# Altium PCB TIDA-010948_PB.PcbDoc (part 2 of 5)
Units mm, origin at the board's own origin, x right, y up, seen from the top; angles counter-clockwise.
Board outline 140 x 180 mm, 4 copper layers (Top Layer, Mid-Layer 1, Mid-Layer 2, Bottom Layer), stack 1.554 mm thick; 481 components, 274 nets, 1278 pads, 301 vias.
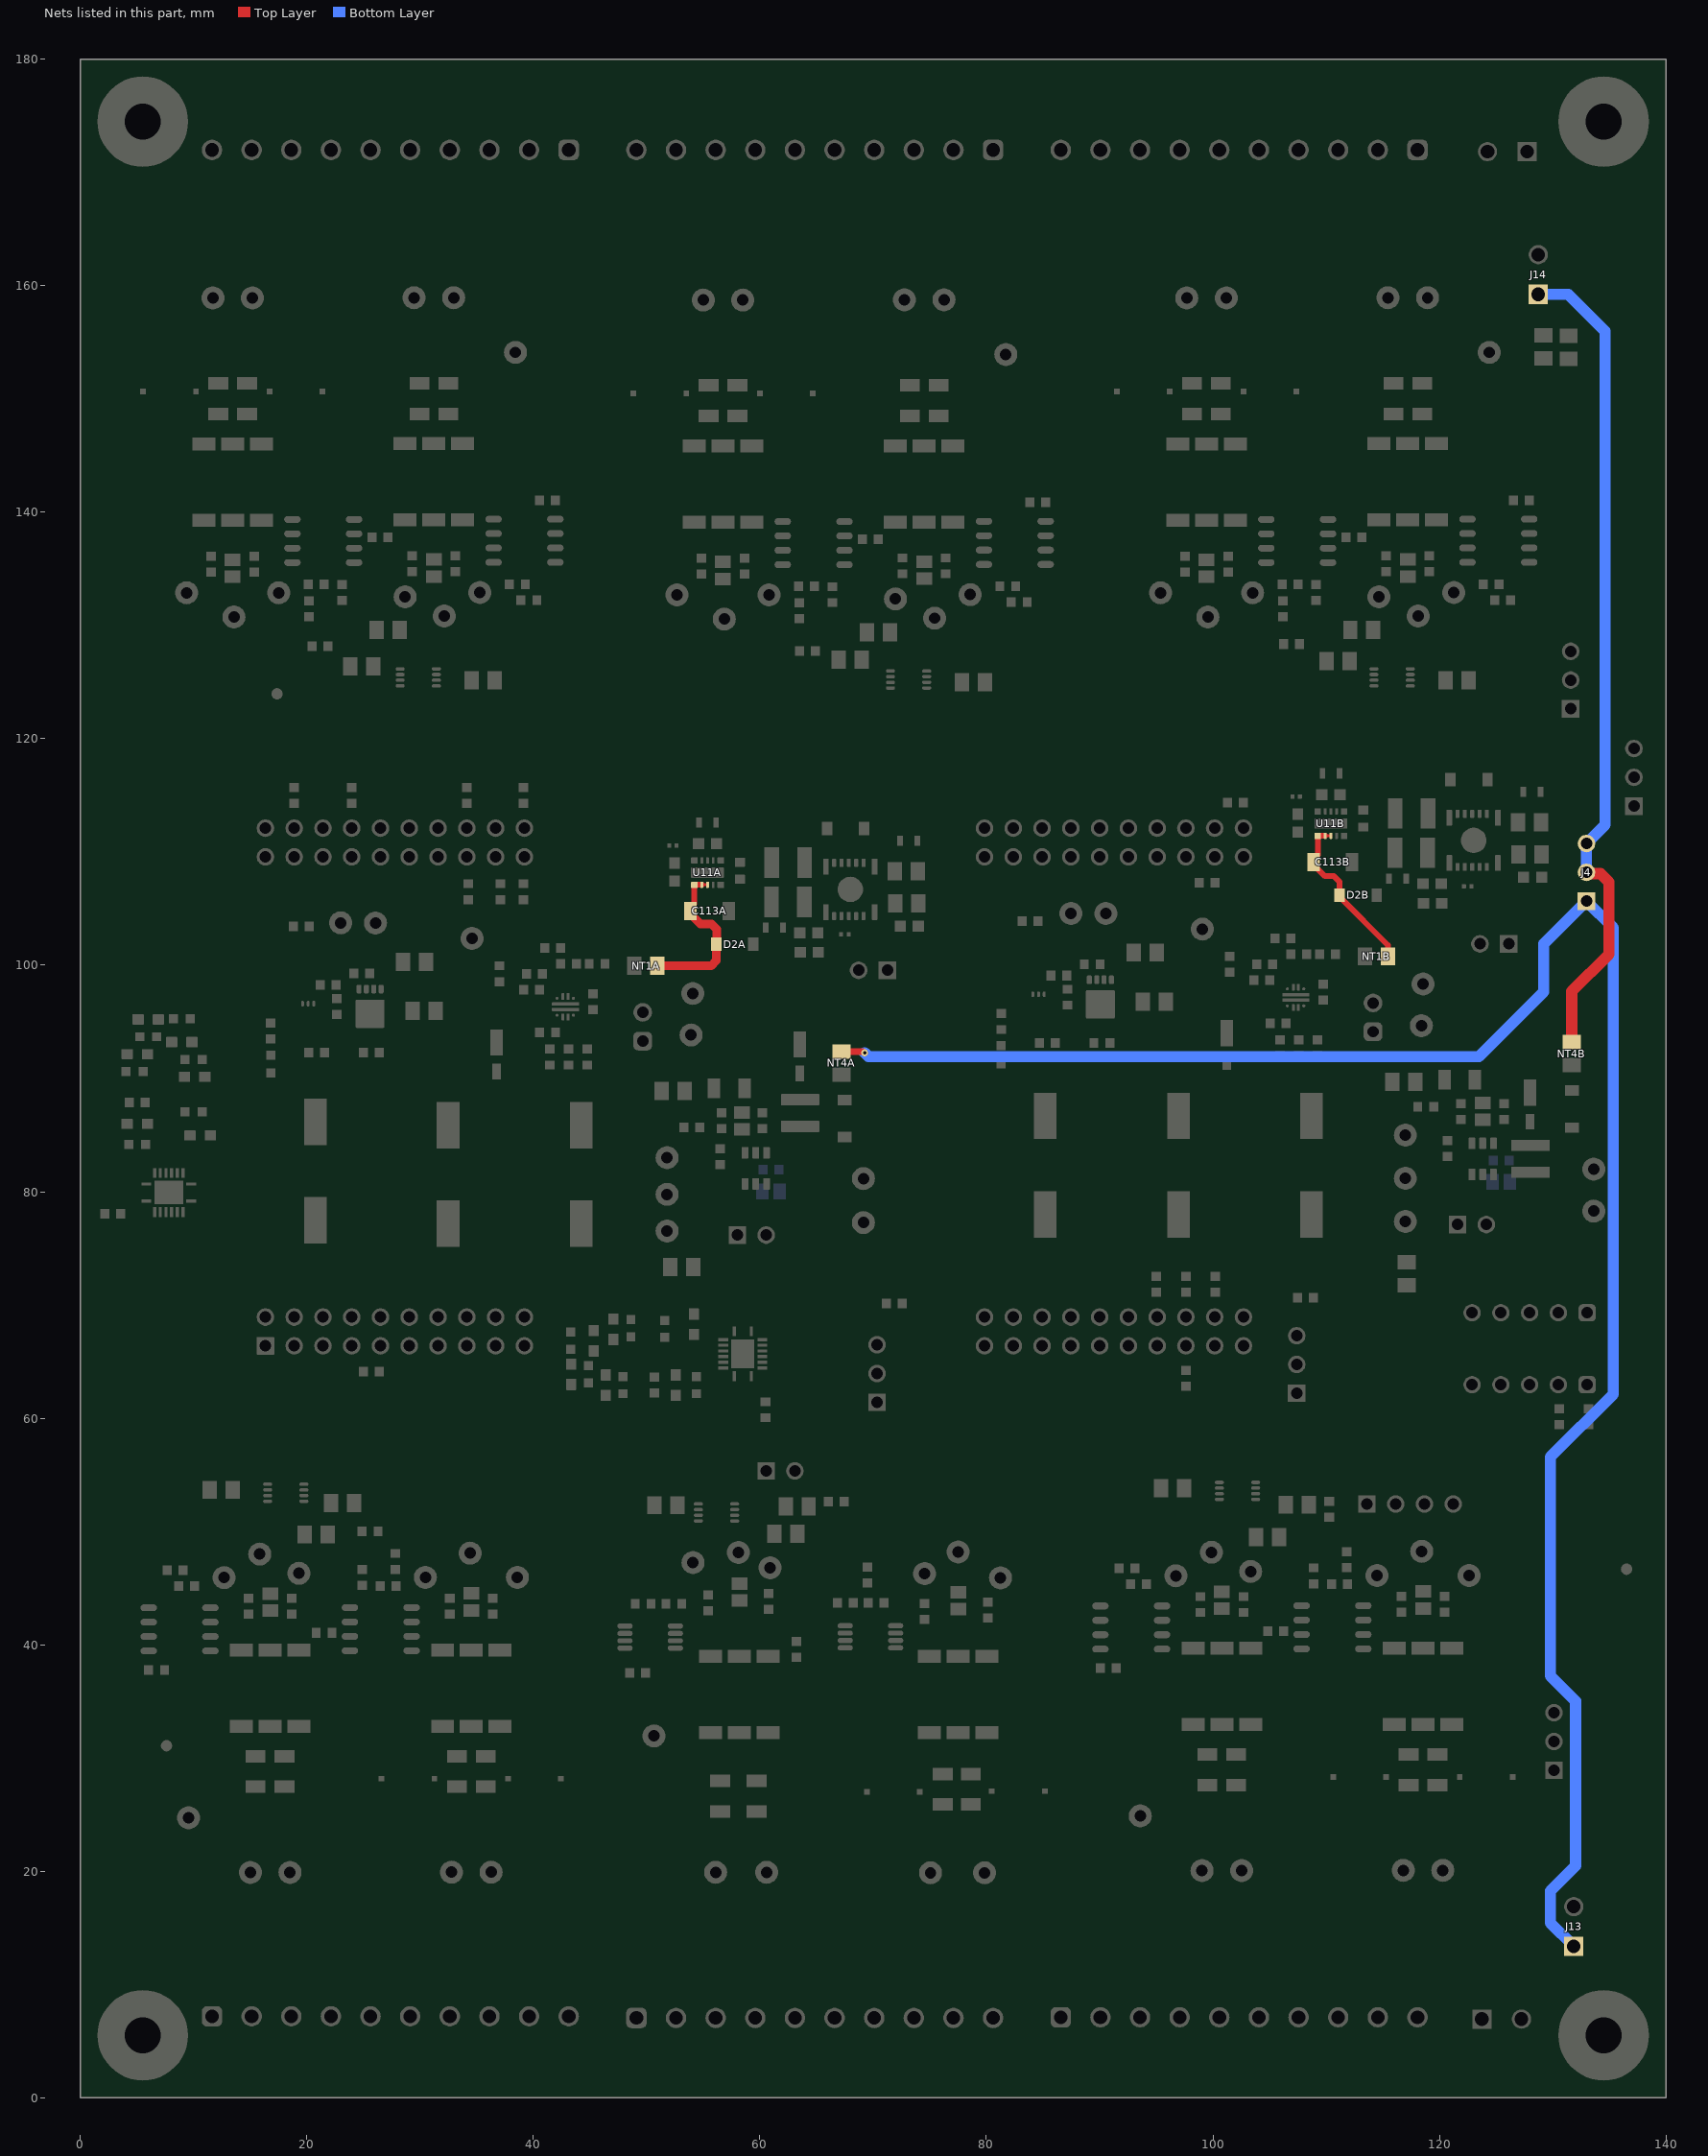
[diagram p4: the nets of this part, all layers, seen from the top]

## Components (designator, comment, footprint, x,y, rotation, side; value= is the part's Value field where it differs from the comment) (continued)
TP22B "5004" Keystone5004 75.426,130.651 r180 top (schematic designator TP22)
TP22C "5004" Keystone5004 32.126,130.838 r180 top (schematic designator TP22)
TP22D "5004" Keystone5004 15.832,47.999 r0 top (schematic designator TP22)
TP22E "5004" Keystone5004 99.874,48.162 r0 top (schematic designator TP22)
TP23A "5004" Keystone5004 97.694,158.93 r180 top (schematic designator TP23)
TP23B "5004" Keystone5004 54.994,158.743 r180 top (schematic designator TP23)
TP23C "5004" Keystone5004 11.694,158.93 r180 top (schematic designator TP23)
TP23D "5004" Keystone5004 36.264,19.908 r0 top (schematic designator TP23)
TP23E "5004" Keystone5004 120.306,20.07 r0 top (schematic designator TP23)
TP24A "5004" Keystone5004 101.189,158.93 r180 top (schematic designator TP24)
TP24B "5004" Keystone5004 58.489,158.743 r180 top (schematic designator TP24)
TP24C "5004" Keystone5004 15.189,158.93 r180 top (schematic designator TP24)
TP24D "5004" Keystone5004 32.769,19.908 r0 top (schematic designator TP24)
TP24E "5004" Keystone5004 116.811,20.07 r0 top (schematic designator TP24)
TP25A "5004" Keystone5004 115.458,158.95 r180 top (schematic designator TP25)
TP25B "5004" Keystone5004 72.758,158.763 r180 top (schematic designator TP25)
TP25C "5004" Keystone5004 29.458,158.95 r180 top (schematic designator TP25)
TP25D "5004" Keystone5004 18.5,19.887 r0 top (schematic designator TP25)
TP25E "5004" Keystone5004 102.542,20.05 r0 top (schematic designator TP25)
TP26A "5004" Keystone5004 118.958,158.95 r180 top (schematic designator TP26)
TP26B "5004" Keystone5004 76.258,158.763 r180 top (schematic designator TP26)
TP26C "5004" Keystone5004 32.958,158.95 r180 top (schematic designator TP26)
TP26D "5004" Keystone5004 15,19.887 r0 top (schematic designator TP26)
TP26E "5004" Keystone5004 99.042,20.05 r0 top (schematic designator TP26)
TP27A "5000" Keystone5000 69.141,81.161 r270 top (schematic designator TP27)
TP27B "5000" Keystone5000 133.635,81.99 r270 top (schematic designator TP27)
TP29A "5001" Keystone5001 69.141,77.274 r270 top (schematic designator TP29)
TP29B "5001" Keystone5001 133.635,78.287 r270 top (schematic designator TP29)
TP30A "5000" Keystone5000 53.919,93.841 r270 top (schematic designator TP30)
TP30B "5000" Keystone5000 118.413,94.67 r270 top (schematic designator TP30)
TP33A "5000" Keystone5000 54.073,97.512 r270 top (schematic designator TP33)
TP33B "5000" Keystone5000 118.566,98.34 r270 top (schematic designator TP33)
TP34A "5002" Keystone5002 34.58,102.363 r90 top (schematic designator TP34)
TP34B "5002" Keystone5002 99.074,103.192 r90 top (schematic designator TP34)
TP35AA "5002" Keystone5002 51.8,83 r90 top (schematic designator TP35A)
TP35AB "5002" Keystone5002 117,85 r90 top (schematic designator TP35A)
TP36A "5000" Keystone5000 26.051,103.738 r90 top (schematic designator TP36)
TP36B "5000" Keystone5000 90.545,104.567 r90 top (schematic designator TP36)
TP37A "5000" Keystone5000 51.8,79.768 r270 top (schematic designator TP37)
TP37B "5000" Keystone5000 117,81.182 r270 top (schematic designator TP37)
TP38A "5001" Keystone5001 22.976,103.746 r270 top (schematic designator TP38)
TP38B "5001" Keystone5001 87.469,104.575 r270 top (schematic designator TP38)
TP39A "5001" Keystone5001 51.8,76.535 r270 top (schematic designator TP39)
TP39B "5001" Keystone5001 117,77.364 r270 top (schematic designator TP39)
U2 "SN74LVC2G126DCUR" DCU0008A_N 56.166,51.677 r0 top
U3 "THVD1550DGKR" DGK0008A_N 50.307,40.668 r0 top
U4A "THVD1450D" D0008A_N 107.44,137.467 r180 top (schematic designator U4)
U4B "THVD1450D" D0008A_N 64.741,137.28 r180 top (schematic designator U4)
U4C "THVD1450D" D0008A_N 21.44,137.467 r180 top (schematic designator U4)
U4D "THVD1450D" D0008A_N 26.518,41.371 r0 top (schematic designator U4)
U4E "THVD1450D" D0008A_N 110.56,41.533 r0 top (schematic designator U4)
U5A "THVD1450D" D0008A_N 125.209,137.487 r180 top (schematic designator U5)
U5B "THVD1450D" D0008A_N 82.509,137.3 r180 top (schematic designator U5)
U5C "THVD1450D" D0008A_N 39.209,137.487 r180 top (schematic designator U5)
U5D "THVD1450D" D0008A_N 8.749,41.35 r0 top (schematic designator U5)
U5E "THVD1450D" D0008A_N 92.791,41.513 r0 top (schematic designator U5)
U6A "TLV61048DBVR" DBV0006A_N 59.63,82.067 r270 top (schematic designator U6)
U6B "TLV61048DBVR" DBV0006A_N 123.827,82.895 r270 top (schematic designator U6)
U8A "TPS259474LRPWT" RPW0010A-MFG 42.831,96.334 r270 top (schematic designator U8)
U8B "TPS259474LRPWT" RPW0010A-MFG 107.325,97.162 r270 top (schematic designator U8)
U9 "THVD1550DGKR" DGK0008A_N 69.753,40.695 r0 top
U10A "SN74LVC2G126DCUR" DCU0008A_N 115.827,125.422 r180 top (schematic designator U10)
U10B "SN74LVC2G126DCUR" DCU0008A_N 73.128,125.235 r180 top (schematic designator U10)
U10C "SN74LVC2G126DCUR" DCU0008A_N 29.827,125.422 r180 top (schematic designator U10)
U10D "SN74LVC2G126DCUR" DCU0008A_N 18.131,53.416 r0 top (schematic designator U10)
U10E "SN74LVC2G126DCUR" DCU0008A_N 102.173,53.578 r0 top (schematic designator U10)
U11A "TPSM82903SISR" SIS0011A-MFG 55.374,108.18 r90 top (schematic designator U11)
U11B "TPSM82903SISR" SIS0011A-MFG 110.42,112.507 r90 top (schematic designator U11)
U14A "TPSM560R6HRDAR" RDA0015A-MFG 67.983,106.697 r270 top (schematic designator U14)
U14B "TPSM560R6HRDAR" RDA0015A-MFG 123.029,111.024 r270 top (schematic designator U14)
U46A "TXB0106RGYR_VQFN16" QFN16_19-68_160X140_1 58.488,65.69 r270 top value=TXB0106RGYR (schematic designator U46)
U46B "TXB0106RGYR_VQFN16" QFN16_19-68_160X140_1 7.796,79.931 r180 top value=TXB0106RGYR (schematic designator U46)
ZZ1 "This Assembly Note is for PCB labels only" AssemblyNoteLabel 350.104,287.343 r0 top
ZZ2 "These assemblies are ESD sensitive, ESD precautions shall be observed." AssemblyNote 350.104,284.578 r0 top
ZZ3 "These assemblies must be clean and free from flux and all contaminants. Use of no clean flux is not acceptable." AssemblyNote 350.104,282.328 r0 top
ZZ4 "These assemblies must comply with workmanship standards IPC-A-610 Class 2, unless otherwise specified." AssemblyNote 350.104,280.079 r0 top

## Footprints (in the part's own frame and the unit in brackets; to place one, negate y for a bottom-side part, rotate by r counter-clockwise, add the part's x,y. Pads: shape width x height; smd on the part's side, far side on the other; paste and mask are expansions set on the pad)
0603 [mm] "0603 from SM-752 data"
  rect 1x0.95 smd: 1(-0.8,0) 2(0.8,0)
  silkscreen extent -1.52,-0.69 1.52,0.69, body extent -0.87,-0.47 0.87,0.47, height 1
0603_HR [mm] "0603"
  rect 0.5x0.9 smd: 1(-0.75,0) 2(0.75,0)
  silkscreen extent -1.35,-0.75 1.35,0.77, body extent -0.82,-0.47 0.82,0.47, height 0.5
0603L [mm] "0603 from SM-752 data"
  rect 0.8x0.85 smd: 1(-0.7,0) 2(0.7,0)
  silkscreen extent -0.07,-0.33 0.07,0.33, body extent -0.87,-0.47 0.87,0.47, height 1
0603S [mil]
  rect 20x35 smd: 1(-30,0) 2(30,0)
  body extent -34,-19 34,19, height 39
0805_HV [mil] "0805 with 30mil clearance between pads"
  rect 50x63 smd: 1(-40,0) 2(40,0)
  silkscreen extent -74,-40 74,40, body extent -43,-29 43,29, height 57
0805L [mm] "0805 from SM-752 data"
  rect 1.1x1.4 smd: 1(-0.75,0) 2(0.75,0)
  body extent -1.1,-0.72 1.1,0.72, height 1.45
1206_180 [mm] "1206_180"
  rect 1.1x1.6 smd: 1(-1.7,0) 2(1.7,0)
  silkscreen extent -0.9,-1 0.9,1, body extent -1.75,-0.95 1.75,0.95, height 1.8
1206L [mm] "1206 from SM-752 data"
  rect 1.1x1.75 smd: 1(-1.35,0) 2(1.35,0)
  silkscreen extent -0.4,-0.77 0.4,0.77, body extent -1.7,-0.9 1.7,0.9, height 1.35
1210_270 [mm] "1210"
  rect 1.3x2.7 smd: 1(-1.45,0) 2(1.45,0)
  silkscreen extent -2.32,-1.57 2.32,1.57, body extent -1.7,-1.35 1.7,1.35, height 2.7
AssemblyNote [mm] "Assembly Note"
AssemblyNoteLabel [mm] "Assembly Note for PCB Labels"
BoosterPack_40pin_J1J3 [mm] "Receptacle, 2.54mm, 10x2, TH"
  rrect6% 1.55x1.55 hole 1.02: 1(1.27,11.43)
  round 1.55 hole 1.02: 2(1.27,8.89) 3(1.27,6.35) 4(1.27,3.81) 5(1.27,1.27) 6(1.27,-1.27) 7(1.27,-3.81) 8(1.27,-6.35) 9(1.27,-8.89) 10(1.27,-11.43) 21(-1.27,11.43) 22(-1.27,8.89) 23(-1.27,6.35) 24(-1.27,3.81) 25(-1.27,1.27) 26(-1.27,-1.27) 27(-1.27,-3.81) 28(-1.27,-6.35) 29(-1.27,-8.89) 30(-1.27,-11.43)
  silkscreen extent -7.62,-12.95 7.62,12.95, body extent -2.48,-12.95 2.48,12.95, height 8.51
BoosterPack_40pin_J2J4 [mm] "Receptacle, 2.54mm, 10x2, TH"
  round 1.55 hole 1.02: 11(-1.27,-11.43) 12(-1.27,-8.89) 13(-1.27,-6.35) 14(-1.27,-3.81) 15(-1.27,-1.27) 16(-1.27,1.27) 17(-1.27,3.81) 18(-1.27,6.35) 19(-1.27,8.89) 20(-1.27,11.43) 31(1.27,-11.43) 32(1.27,-8.89) 33(1.27,-6.35) 34(1.27,-3.81) 35(1.27,-1.27) 36(1.27,1.27) 37(1.27,3.81) 38(1.27,6.35) 39(1.27,8.89) 40(1.27,11.43)
  silkscreen extent -7.62,-12.95 2.48,12.95, body extent -2.48,-12.95 2.48,12.95, height 8.51
BoosterPack_40pin_J5J7 [mm] "Receptacle, 2.54mm, 10x2, TH"
  round 1.55 hole 1.02: 41(1.27,11.43) 42(1.27,8.89) 43(1.27,6.35) 44(1.27,3.81) 45(1.27,1.27) 46(1.27,-1.27) 47(1.27,-3.81) 48(1.27,-6.35) 49(1.27,-8.89) 50(1.27,-11.43) 61(-1.27,11.43) 62(-1.27,8.89) 63(-1.27,6.35) 64(-1.27,3.81) 65(-1.27,1.27) 66(-1.27,-1.27) 67(-1.27,-3.81) 68(-1.27,-6.35) 69(-1.27,-8.89) 70(-1.27,-11.43)
  silkscreen extent -7.62,-12.95 7.62,12.95, body extent -2.48,-12.95 2.48,12.95, height 8.51
BoosterPack_40pin_J6J8 [mm] "Receptacle, 2.54mm, 10x2, TH"
  round 1.55 hole 1.02: 51(-1.27,-11.43) 52(-1.27,-8.89) 53(-1.27,-6.35) 54(-1.27,-3.81) 55(-1.27,-1.27) 56(-1.27,1.27) 57(-1.27,3.81) 58(-1.27,6.35) 59(-1.27,8.89) 60(-1.27,11.43) 71(1.27,-11.43) 72(1.27,-8.89) 73(1.27,-6.35) 74(1.27,-3.81) 75(1.27,-1.27) 76(1.27,1.27) 77(1.27,3.81) 78(1.27,6.35) 79(1.27,8.89) 80(1.27,11.43)
  silkscreen extent -7.62,-12.95 2.48,12.95, body extent -2.48,-12.95 2.48,12.95, height 8.51
CE_Mark_5mm [mm] "Minimum text height for CE Mark"
  silkscreen extent -3.5,-2.5 3.5,2.5
D0008A_N [mm] "SOIC, 8-Leads, Body 4.9x3.9mm, Pitch 1.27mm, IPC Medium Density"
  oval 1.45x0.6 smd: 1(-2.725,1.905) 2(-2.725,0.635) 3(-2.725,-0.635) 4(-2.725,-1.905) 5(2.725,-1.905) 6(2.725,-0.635) 7(2.725,0.635) 8(2.725,1.905)
  silkscreen extent -3.3,-2.5 0.9,2.5, body extent -3,-2.45 3,2.45, height 1.63
DBV0006A_N [mm] "SOT23, 6-Leads, Body 2.9x1.6mm, Pitch 0.95mm, Lead Span 2.8mm, IPC Medium Density"
  rrect17% 1x0.6 smd: 1(-1.375,0.95) 2(-1.375,0) 3(-1.375,-0.95) 4(1.375,-0.95) 5(1.375,0) 6(1.375,0.95)
  silkscreen extent -1.68,-1.55 0.5,1.55, body extent -1.42,-1.46 1.42,1.46, height 1.12
DCU0008A_N [mm] "TSSOP, 8-Leads, Body 2x2.3mm, Pitch 0.5mm, IPC Medium Density"
  oval 0.8x0.3 smd: 1(-1.6,0.75) 2(-1.6,0.25) 3(-1.6,-0.25) 4(-1.6,-0.75) 5(1.6,-0.75) 6(1.6,-0.25) 7(1.6,0.25) 8(1.6,0.75)
  silkscreen extent -1.05,-1.05 0.38,1.05, body extent -1.56,-1 1.56,1, height 0.9
DGK0008A_N [mm] "TSOP, 8-Leads, Body 3x3mm, Pitch 0.65mm, IPC Medium Density"
  oval 1.35x0.45 smd: 1(-2.225,0.975) 2(-2.225,0.325) 3(-2.225,-0.325) 4(-2.225,-0.975) 5(2.225,-0.975) 6(2.225,-0.325) 7(2.225,0.325) 8(2.225,0.975)
  silkscreen extent -2.75,-1.55 0.95,1.55, body extent -2.45,-1.5 2.45,1.5, height 0.96
DO-216AA [mm] "ST Microelectronics"
  rect 2.32x1.1 smd: 1(-1.16,0)
  rect 1.38x0.75 smd: 2(1.4,0)
  Top Layer region: -1.82,-1.015 0,-1.015 0,1.015 -1.82,1.015
  silkscreen extent -2.58,-1.1 0.63,1.15, body extent -2,-1 1.85,1, height 1.01
DQG0008A [mm] "SMD, 8-Leads, Body 3.3x3.3mm, Pitch 0.65mm"
  rrect45% 0.75x0.44 smd paste-0.05 mask-0.05: 1(-1.525,0.975) 2(-1.525,0.325) 3(-1.525,-0.325) 4(-1.525,-0.975) 5(1.525,-0.975) 6(1.525,-0.325) 7(1.525,0.325) 8(1.525,0.975)
  rrect15% 0.676x1.125 on Top Paste: 9(-0.212,0.662) 9(-0.212,-0.663) 9(0.664,0.662) 9(0.664,-0.663)
  rrect6% 1.775x2.45 on Top Solder: 9(0.327,0)
  rrect8% 2.5x2.55 smd paste-1.5 mask-1.5: 9(0.65,0)
  rrect29% 0.5x0.34 on Top Solder: 9(1.175,0.975) 9(1.175,-0.325) 9(1.175,0.325) 9(1.175,-0.975)
  silkscreen extent -1.8,-1.8 1.8,1.8, body extent -1.65,-1.65 1.65,1.65, height 1.1
FCC_disclaimer [mm]
Fiducial10-20 [mm]
  round 1 smd mask+0.5: 1(0,0)
  Top Layer keep-out circle w1.178: c0,0 r0.5
FP-CC0603KRX7R7BB102_0603-MFG [mm]
  rrect13% 0.8x0.9 smd paste+0 mask+0: 1(-0.75,0) 2(0.75,0)
  silkscreen extent -0.85,-0.85 0.85,0.85, body extent -0.8,-0.4 0.8,0.4, height 0.9
FP-RE0201BRE07100KL_0201-MFG [mm]
  rrect29% 0.35x0.4 smd paste+0 mask+0: 1(-0.325,0) 2(0.325,0)
  silkscreen extent -0.33,-0.58 0.33,0.58, body extent -0.6,-0.3 0.6,0.3, height 0.25
FP-RN73C1J49K9BTG_0603-MFG [mm]
  rrect11% 1x0.9 smd paste+0 mask+0: 1(-0.9,0) 2(0.9,0)
  silkscreen extent -0.77,-0.82 0.77,0.82, body extent -1.5,-0.55 1.5,0.55, height 0.25
FP-XAL4030-472MEC_SMD2-MFG [mm]
  rrect10% 0.98x3.4 smd paste+0 mask+0: 1(-1.185,0) 2(1.185,0)
  silkscreen extent -2.15,-2.15 2.15,2.15, body extent -2.25,-2.25 2.25,2.25, height 0.25
Keystone5000 [mil] "For Keystone 500x miniature loop terminals"
  round 80 hole 40: 1(0,0)
  silkscreen extent -52,-52 52,52, body extent -49,-49 49,49, height 182
Keystone5001 [mil] "For Keystone 500x miniature loop terminals"
  round 80 hole 40: 1(0,0)
  silkscreen extent -52,-52 52,52, body extent -49,-49 49,49, height 182
Keystone5002 [mil] "For Keystone 500x miniature loop terminals"
  round 80 hole 40: 1(0,0)
  silkscreen extent -52,-52 52,52, body extent -49,-49 49,49, height 182
Keystone5004 [mil] "For Keystone 500x miniature loop terminals"
  round 80 hole 40: 1(0,0)
  silkscreen extent -52,-52 52,52, body extent -49,-49 49,49, height 182
Keystone_1902C [mil] "Hex Standoff, 4-40 threaded, nylon"
  round 1 on Mech4: 0(0,0)
  body extent -145,-126 146,126, height 501
Label_650x200 [mil] "Thermal Transfer Label"
  round 1 on Mech13: 0(0,0)
  silkscreen extent -325,-100 325,100, body extent -325,-100 325,100, height 1
Net-Tie_0805_HV_NoOverlay [mil] "0805_HV pads tied by 10mil copper trace which can be cut.  An 0805 part can be placed on pads."
  rect 50x63 smd paste-25: 1(-40,0) 2(40,0)
  Top Layer lines w10: 16,0 -16,0
  Top Layer keep-out lines w1: 22,30.91 22,-30.91 ; 14.96,30.91 -14.96,30.91 ; 14.96,-30.91 -14.96,-30.91 ; -22,30.91 -22,-30.91
"NY PMS 440 0025 PH" [mm] "4-40 nylon screw and mounting hole"
  round 8 hole 3.2: 1(0,0)
  body extent -3.3,-3.3 3.3,3.3, height 2.69
On-Shore_ED555_10DS [mm] "Terminal Block, 3.5mm, 10x1, TH"
  rrect50% 1.8x1.8 hole 1.2: 1(-15.75,0)
  round 1.8 hole 1.2: 2(-12.25,0) 3(-8.75,0) 4(-5.25,0) 5(-1.75,0) 6(1.75,0) 7(5.25,0) 8(8.75,0) 9(12.25,0) 10(15.75,0)
  body extent -17.5,-3.8 17.5,2.7, height 8.2
Phoenix_1984617 [mm] "Terminal Block, 3.5mm, 2x1, TH"
  rect 1.7x1.7 hole 1.2: 1(-1.75,0)
  round 1.7 hole 1.2: 2(1.75,0)
  silkscreen extent -3.5,-4.5 4.07,3.1, body extent -3.5,-4.5 4.07,3.1, height 9
PULSE_PE-68386NL [mil] "PULSE"
  rect 45x80 smd: 1(-132.5,100) 2(-132.5,0) 3(-132.5,-100) 4(132.5,-100) 5(132.5,0) 6(132.5,100)
  silkscreen extent -98,-134 98,148, body extent -177,-133 177,133, height 99
QFN16_19-68_160X140_1 [mil] "QFN16_19-68_160X140_1"
  rect 34x11 smd: 1(77.76,29.53) 8(-77.76,29.53) 9(-77.76,-29.53) 16(77.76,-29.53)
  rect 11x34 smd: 2(49.21,67.91) 3(29.53,67.91) 4(9.84,67.91) 5(-9.84,67.91) 6(-29.53,67.91) 7(-49.21,67.91) 10(-49.21,-67.91) 11(-29.53,-67.91) 12(-9.84,-67.91) 13(9.84,-67.91) 14(29.53,-67.91) 15(49.21,-67.91)
  rect 100x81 smd: 17(0,0)
  silkscreen extent -90,-80 122,80, body extent -80,-70 80,70, height 150
RDA0015A-MFG [mm]
  rrect20% 1.4x0.5 smd paste-1000 mask+0: 1(-2,2.145) 7(-2,-2.155) 8(2,-2.155) 14(2,2.145)
  rrect29% 0.7x0.35 smd paste-1000 mask+0: 2(-2.35,1.17) 3(-2.35,0.52) 4(-2.35,-0.13) 5(-2.35,-0.78) 6(-2.35,-1.43) 9(2.35,-1.43) 10(2.35,-0.78) 11(2.35,-0.13) 12(2.35,0.52) 13(2.35,1.17)
  round 2.25 smd paste-1000 mask+0: 15(0,0)
  Top Layer region: -0.7,2.3 -0.725,2.293 -0.743,2.275 -0.75,2.25 -0.75,2.25 -0.75,1.3 -0.754,1.281 -0.765,1.265 -0.781,1.254 -0.8,1.25 -0.8,1.25 -1.2,1.25 -1.225,1.243 -1.243,1.225 -1.25,1.2 -1.25,1.2 -1.25,-1.2 -1.243,-1.225 -1.225,-1.243 -1.2,-1.25 -1.2,-1.25 -0.8,-1.25 -0.781,-1.254 -0.765,-1.265 -0.754,-1.281 -0.75,-1.3 -0.75,-1.3 -0.75,-2.25 -0.743,-2.275 -0.725,-2.293 -0.7,-2.3 -0.7,-2.3 0.7,-2.3 0.725,-2.293 0.743,-2.275 0.75,-2.25 0.75,-2.25 0.75,-1.3 0.754,-1.281 0.765,-1.265 0.781,-1.254 0.8,-1.25 0.8,-1.25 1.2,-1.25 1.225,-1.243 1.243,-1.225 1.25,-1.2 1.25,-1.2 1.25,1.2 1.243,1.225 1.225,1.243 1.2,1.25 1.2,1.25 0.8,1.25 0.781,1.254 0.765,1.265 0.754,1.281 0.75,1.3 0.75,1.3 0.75,2.25 0.743,2.275 0.725,2.293 0.7,2.3 0.7,2.3
  silkscreen extent -3.37,-2.8 2.55,2.8, body extent -2.8,-2.9 2.8,2.9, height 0.25
RPW0010A-MFG [mm]
  round 0.27 smd paste-1000 mask+0: 1(-0.75,0.7) 10(0.75,0.7)
  rrect40% 0.6x0.25 smd paste+0 mask+0: 2(-0.9,0.225) 3(-0.9,-0.225) 8(0.9,-0.225) 9(0.9,0.225)
  round 0.255 smd paste-1000 mask+0: 4(-0.75,-0.75) 7(0.75,-0.75)
  rrect33% 0.3x2.4 smd paste-1000 mask+0: 5(-0.25,0) 6(0.25,0)
  Top Layer region: 0.85,0.85 0.85,1.15 0.846,1.169 0.835,1.185 0.819,1.196 0.8,1.2 0.8,1.2 0.65,1.2 0.631,1.196 0.615,1.185 0.604,1.169 0.6,1.15 0.6,1.15 0.6,0.6 0.604,0.581 0.615,0.565 0.631,0.554 0.65,0.55 0.65,0.55 1.15,0.55 1.169,0.554 1.185,0.565 1.196,0.581 1.2,0.6 1.2,0.6 1.2,0.8 1.196,0.819 1.185,0.835 1.169,0.846 1.15,0.85 1.15,0.85
  Top Layer region: 0.85,-0.85 0.85,-1.15 0.846,-1.169 0.835,-1.185 0.819,-1.196 0.8,-1.2 0.8,-1.2 0.65,-1.2 0.631,-1.196 0.615,-1.185 0.604,-1.169 0.6,-1.15 0.6,-1.15 0.6,-0.6 0.604,-0.581 0.615,-0.565 0.631,-0.554 0.65,-0.55 0.65,-0.55 1.15,-0.55 1.169,-0.554 1.185,-0.565 1.196,-0.581 1.2,-0.6 1.2,-0.6 1.2,-0.8 1.196,-0.819 1.185,-0.835 1.169,-0.846 1.15,-0.85 1.15,-0.85
  Top Layer region: -0.85,-0.85 -0.85,-1.15 -0.846,-1.169 -0.835,-1.185 -0.819,-1.196 -0.8,-1.2 -0.8,-1.2 -0.65,-1.2 -0.631,-1.196 -0.615,-1.185 -0.604,-1.169 -0.6,-1.15 -0.6,-1.15 -0.6,-0.6 -0.604,-0.581 -0.615,-0.565 -0.631,-0.554 -0.65,-0.55 -0.65,-0.55 -1.15,-0.55 -1.169,-0.554 -1.185,-0.565 -1.196,-0.581 -1.2,-0.6 -1.2,-0.6 -1.2,-0.8 -1.196,-0.819 -1.185,-0.835 -1.169,-0.846 -1.15,-0.85 -1.15,-0.85
  Top Layer region: -0.85,0.85 -0.85,1.15 -0.843,1.175 -0.825,1.193 -0.8,1.2 -0.8,1.2 -0.65,1.2 -0.631,1.196 -0.615,1.185 -0.604,1.169 -0.6,1.15 -0.6,1.15 -0.6,0.6 -0.604,0.581 -0.615,0.565 -0.631,0.554 -0.65,0.55 -0.65,0.55 -1.15,0.55 -1.169,0.554 -1.185,0.565 -1.196,0.581 -1.2,0.6 -1.2,0.6 -1.2,0.8 -1.193,0.825 -1.175,0.843 -1.15,0.85 -1.15,0.85
  silkscreen extent -1.87,-1.58 1.05,1.58, body extent -1.3,-1.3 1.3,1.3, height 0.25
Samtec_SSQ-105-01-x-S [mm] "Receptacle, 2.54mm, 5x1, TH"
  rrect50% 1.53x1.53 hole 1.02: 1(-5.08,0)
  round 1.53 hole 1.02: 2(-2.54,0) 3(0,0) 4(2.54,0) 5(5.08,0)
  silkscreen extent -6.61,-1.2 6.61,1.65, body extent -6.6,-1.21 6.6,1.21, height 8.51
SIS0011A-MFG [mm]
  rrect18% 0.55x0.575 smd paste+0 mask+0: 1(-1.075,1.162) 5(-1.075,-1.162) 6(1.075,-1.162) 10(1.075,1.162)
  rrect40% 0.55x0.25 smd paste+0 mask+0: 2(-1.075,0.5) 3(-1.075,0) 4(-1.075,-0.5) 7(1.075,-0.5) 8(1.075,0) 9(1.075,0.5)
  rrect11% 0.9x2.9 smd paste-1000 mask+0: 11(0,0)
  silkscreen extent -2.02,-1.83 1.45,1.83, body extent -1.4,-1.5 1.4,1.5, height 1.6
SM_RADIAL_G [mm] "10 x 10.2mm:  Panasonic G"
  rect 4.1x2 smd: 1(-4.35,0) 2(4.35,0)
  silkscreen extent -5.35,-5.35 5.35,5.35, body extent -5.25,-5.25 5.25,5.25, height 10.5
SOD-123 [mm] "On Semi recommended land pattern"
  rect 0.915x1.22 smd: 1(-1.637,0) 2(1.637,0)
  silkscreen extent -2.74,-1.17 2.03,1.17, body extent -1.93,-0.9 1.93,0.9, height 1.35
Sullins_Gxx02SAAN [mm] "Header, 2.54 mm, 2x1, TH"
  rect 1.55x1.55 hole 1.016: 1(-1.27,0)
  round 1.55 hole 1.016: 2(1.27,0)
  silkscreen extent -2.54,-1.75 2.54,1.27, body extent -2.54,-1.27 2.54,1.27, height 8.38
Sullins_Gxx03SAAN [mm] "Header, 2.54 mm, 3x1, TH"
  rect 1.55x1.55 hole 1.016: 1(-2.54,0)
  round 1.55 hole 1.016: 2(0,0) 3(2.54,0)
  silkscreen extent -3.81,-1.74 3.81,1.27, body extent -3.81,-1.27 3.81,1.27, height 8.38
Sullins_xxC04SAAN [mm] "Header, 2.54 mm, 4x1, TH"
  rect 1.55x1.55 hole 1.016: 1(-3.81,0)
  round 1.55 hole 1.016: 2(-1.27,0) 3(1.27,0) 4(3.81,0)
  silkscreen extent -5.08,-1.27 5.08,1.6, body extent -5.08,-1.27 5.08,1.27, height 8.38
TSW-102-07-G-S [mm] "Samtec 100mil, 1x2, 230 mil above insulator"
  rrect50% 1.65x1.65 hole 1.016: 1(-1.27,0)
  round 1.65 hole 1.016: 2(1.27,0)
  silkscreen extent -3.17,-1.27 2.54,1.27, body extent -2.54,-1.27 2.54,1.27, height 8.38
WCAP-CSGP_0603_L1.6W0.8H0.8_Reflow [mm] "Ceramic Capacitors, body 1.6x0.8mm"
  rect 0.8x0.8 smd: 1(-0.75,0) 2(0.75,0)
  body extent -0.8,-0.4 0.8,0.4, height 0.8
WE-TPC_4828 [mm] "Wurth Elektronik recommended land pattern"
  rect 0.5x0.5 smd: 1(-2.35,0) 2(2.325,0)
  Top Layer region: -0.75,1.64 -1.005,1.504 -1.279,1.279 -1.504,1.005 -1.671,0.692 -1.774,0.353 -1.809,0 -1.774,-0.353 -1.671,-0.692 -1.504,-1.005 -1.279,-1.279 -1.005,-1.504 -0.75,-1.64 -0.75,-2.65 -2.75,-2.65 -2.75,2.65 -0.75,2.65
  Top Layer region: 0.75,1.64 1.005,1.504 1.279,1.279 1.504,1.005 1.671,0.692 1.774,0.353 1.809,0 1.774,-0.353 1.671,-0.692 1.504,-1.005 1.279,-1.279 1.005,-1.504 0.75,-1.64 0.75,-2.65 2.75,-2.65 2.75,2.65 0.75,2.65
  silkscreen extent -0.5,-2.6 0.5,2.63, body extent -2.5,-2.5 2.5,2.5, height 2
WEEE_Minimum [mm] "WEEElie bin"
  silkscreen extent -2.42,-4.38 2.52,2.65
WL-SMCW_GREEN [mm] "WURTH"
  rect 0.8x0.8 smd: 1(-0.8,0) 2(0.8,0)
  silkscreen extent -1.9,-0.8 1.2,0.8, body extent -0.85,-0.45 0.85,0.45, height 0.8
YJK0003A [mm] "SMD, 3-Leads, Body 1.49x0.73mm"
  rrect50% 0.2x0.39 on Top Paste: 1(-0.525,0) 2(0,0) 3(0.525,0)
  rrect80% 0.25x0.49 smd paste-0.15 mask-0.05: 1(-0.5,0) 2(0,0) 3(0.5,0)
  silkscreen extent -0.9,-0.5 0.9,0.5, body extent -0.75,-0.37 0.74,0.36, height 0.35

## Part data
C1A C1B C2A C2B C8A C8B C8C C8D C8E C9A C9B C9C C9D C9E C18A C18B C22A C22B C24A C24B C30A C30B C31A C31B C33 C37: library part CMP-0007469-4, "CAP, CERM, 0.1 uF, 100 V, +/- 10%, X7R, 0603", Cap_Case=0603, Manufacturer=MuRata, Supplier Part Number 1=490-3285-1-ND, TempCo=X7R, Tolerance_%=10%, Value1=Unknown, Value2=100V, ValueDisplayed=0.1uF
C3A C3B C4A C4B C5A C5B C6A C6B C7A C7B C16A C16B: library part CMP-0118906-1, "WCAP-CSGP Multilayer Ceramic Chip Capacitor, General Purpose, size 0603, NP0, 1nF, 100VDC", Capacitance Tolerance=+/-5%, Case/Size Code=0603, Insulation Resistance=10GOhm, Manufacturer="Wurth Elektronik", Operating Temperature Max=125°C, Operating Temperature Min=-55°C, Rated Voltage (DC)=100V
C10A C10B C10C C10D C10E C11A C11B C11C C11D C11E C32 C36: library part CMP-0007977-2, "CAP, CERM, 2.2 uF, 50 V, +/- 10%, X7R, AEC-Q200 Grade 1, 0805", Cap_Case=0805, Manufacturer=TDK, Supplier Part Number 1=445-174216-1-ND, TempCo=X7R, Tolerance_%=10%, Value1="0.003288 ohm", Value2=50V, ValueDisplayed=2.2uF
C12A C12B C12C C12D C12E C13A C13B C13C C13D C13E C14A C14B C14C C14D C14E C15A C15B C15C C15D C15E C21 C23 C34 C35: library part CMP-0012479-3, "CAP, Film, 0.47 uF, 16 V, +/- 20%, 1206 SMD", Cap_Case=1206, Manufacturer=Panasonic, Supplier Part Number 1=PCF1130CT-ND, Tolerance_%=20%, Value1=Unknown, Value2=16V, ValueDisplayed=0.47uF
C20A C20B C28A C28B C29A C29B: library part CMP-0010708-1, "CAP, AL, 680 uF, 16 V, +/- 20%, 0.08 ohm, AEC-Q200 Grade 2, SMD", Cap_Case=G, Manufacturer=Panasonic, Supplier Part Number 1=PCE3794CT-ND, Tolerance_%=20%, Value1="0.08 ohm", Value2=16V, ValueDisplayed=680uF
C25A C25B: library part CMP-0007198-4, "CAP, CERM, 2200 pF, 50 V, +/- 5%, C0G/NP0, 0603", Cap_Case=0603, Manufacturer=MuRata, Supplier Part Number 1=490-1459-1-ND, TempCo=C0G/NP0, Tolerance_%=5%, Value1=Unknown, Value2=50V, ValueDisplayed=2200pF
C26A C26B: library part CMP-0007459-4, "CAP, CERM, 5600 pF, 50 V, +/- 10%, X7R, 0603", Cap_Case=0603, Manufacturer=MuRata, Supplier Part Number 1=490-1507-1-ND, TempCo=X7R, Tolerance_%=10%, Value1=Unknown, Value2=50V, ValueDisplayed=5600pF
C27A C27B: library part CMP-0007147-5, "CAP, CERM, 0.015 uF, 100 V, +/- 10%, X7R, AEC-Q200 Grade 1, 0603", Cap_Case=0603, Manufacturer=MuRata, Supplier Part Number 1=490-8029-1-ND, TempCo=X7R, Tolerance_%=10%, Value1=Unknown, Value2=100V, ValueDisplayed=0.015uF
C46A C46B: library part CMP-0094870-1, "1000 pF ±10% 16V Ceramic Capacitor X7R 0603 (1608 Metric)", Digikey Part Number=311-4063-1-ND, Manufacturer=YAGEO, Mouser Part Number=603-CC603KRX7R7BB102, Operating Temperature Range="-55°C to +125°C", TempCo=15%, Temperature Characteristic=X7R, Tolerance_%=10%, ValueDisplayed="1.0 nF", Voltage=16V
C50A C50B C51A C51B: library part CMP-0008264-2, "CAP, CERM, 4.7 uF, 50 V, +/- 10%, X7S, 0805", Cap_Case=0805, Manufacturer=MuRata, Supplier Part Number 1=GRM21BC71H475KE11K-ND, TempCo=X7S, Tolerance_%=10%, Value1=Unknown, Value2=50V, ValueDisplayed=4.7uF
C59A C59B C60A C60B: library part CMP-0009211-1, "CAP, CERM, 47 uF, 16 V, +/- 10%, X5R, 1210", Cap_Case=1210, Manufacturer=MuRata, Supplier Part Number 1=GRM32ER61C476KE15L-ND, TempCo=X5R, Tolerance_%=10%, Value1=Unknown, Value2=16V, ValueDisplayed=47uF
C113A C113B: library part CMP-0085573-1, "CAP, CERM, 10 µF, 25 V,+/- 10%, X5R, 1206", Cap_Case=1206, Manufacturer=TDK, TempCo=X5R, Tolerance_%=10%, Value2=25V, ValueDisplayed=10µF
C114A C114B: library part CMP-0007158-4, "CAP, CERM, 22 uF, 10 V, +/- 20%, X5R, 0603", Cap_Case=0603, Manufacturer=MuRata, Supplier Part Number 1=490-13243-1-ND, TempCo=X5R, Tolerance_%=20%, Value1=Unknown, Value2=10V, ValueDisplayed=22uF
C116A C116B: library part CMP-0008315-1, "CAP, CERM, 10 uF, 10 V, +/- 10%, X7R, 0805", Cap_Case=0805, Manufacturer=MuRata, Supplier Part Number 1=490-3905-1-ND, TempCo=X7R, Tolerance_%=10%, Value1="0.003 ohm", Value2=10V, ValueDisplayed=10uF
C120A C120B: library part CMP-0008264-1, "CAP, CERM, 4.7 uF, 50 V, +/- 10%, X7S, 0805", Cap_Case=0805, Manufacturer=MuRata, Supplier Part Number 1=GRM21BC71H475KE11K-ND, TempCo=X7S, Tolerance_%=10%, Value1=Unknown, Value2=50V, ValueDisplayed=4.7uF
D1A D1B D2A D2B D6A D6B: library part CMP-0028602-3, "Diode, Schottky, 60 V, 500 mA, SOD-123", Manufacturer="Micro Commercial Components", Value1=0.5A, Value2=0.7V
D3A D3B D9A D9B: library part CMP-0077046-2, "Diode, Schottky, 20 V, 1 A, DO-216-AA", Manufacturer=STMicroelectronics, Value1=1A, Value2=0.49V
D8A D8B: library part CMP-0002905-2, "LED, Green, SMD", Color=Green, Manufacturer="Wurth Elektronik", Value1=W, Value2=3.2V
FID1 FID2 FID3: library part CMP-0077181-1, "Fiducial mark.  There is nothing to buy or mount.", Manufacturer=N/A
H1 H2 H3 H4: library part CMP-0003617-1, "Machine Screw, Round, #4-40 x 1/4, Nylon, Philips panhead", Manufacturer="B&F Fastener Supply", Supplier Part Number 1=H542-ND
H5 H6 H7 H8: library part CMP-0003610-1, "Standoff, Hex, 0.5\"L #4-40 Nylon", Manufacturer=Keystone, Supplier Part Number 1=36-1902C-ND
J1: library part CMP-0003837-4, "Receptacle, 2.54mm, 10x2, Tin, TH", Alternate Manufacturer="Major League Electronics", Alternate PartNumber=CRD-081413-A-G, Manufacturer=Samtec, PartNumber=SSQ-110-03-T-D, Supplier Part Number 1=SAM1204-10-ND
J2: library part CMP-0078266-4, "Receptacle, 2.54mm, 10x2, Tin, TH", Alternate Manufacturer="Major League Electronics", Alternate PartNumber=CRD-081413-A-G, Manufacturer=Samtec, PartNumber=SSQ-110-03-T-D, Supplier Part Number 1=SAM1204-10-ND
J3A J3B J3C J3D J3E J3F: library part CMP-0084189-1, "Terminal Block, 3.5mm, 10x1, TH", Color=Gray, Current_A=6A, Manufacturer="On-Shore Technology", Voltage_V=150V
J4 J7 J8 J10 J15 J17: library part CMP-0054577-1, "Header, 2.54 mm, 3x1, Gold, TH", Manufacturer="Sullins Connector Solutions"
J5: library part CMP-0081070-3, "Receptacle, 2.54mm, 10x2, Tin, TH", Alternate Manufacturer="Major League Electronics", Alternate PartNumber=CRD-081413-A-G, Manufacturer=Samtec, PartNumber=SSQ-110-03-T-D, Supplier Part Number 1=SAM1204-10-ND
J6: library part CMP-0081071-3, "Receptacle, 2.54mm, 10x2, Tin, TH", Alternate Manufacturer="Major League Electronics", Alternate PartNumber=CRD-081413-A-G, Manufacturer=Samtec, PartNumber=SSQ-110-03-T-D, Supplier Part Number 1=SAM1204-10-ND
J9A J9B J16 J26A J26B: library part CMP-0054576-1, "Header, 2.54 mm, 2x1, Gold, TH", Manufacturer="Sullins Connector Solutions"
J11A J11B: library part CMP-0075405-3, "Header, 100mil, 2x1, Gold, TH", Color=Black, Current_A=6.3A, Manufacturer=Samtec, Supplier Part Number 1=SAM1029-02-ND, Voltage_V=550V
J12 J21: library part CMP-0077539-1, "Receptacle, 2.54mm, 5x1, Gold, TH", Color=Black, Current_A=6.3A, Manufacturer=Samtec, PartNumber=SSQ-105-01-G-S, Supplier Part Number 1=SAM1180-05-ND, Voltage_V=550V
J13 J14 J19 J20: library part CMP-0055519-1, "Terminal Block, 3.5mm, 2x1, TH", Color=Green, Current_A=17.5A, Manufacturer="Phoenix Contact", Supplier Part Number 1=277-1721-ND, Voltage_V=200V
J18: library part CMP-0054583-1, "Header, 2.54 mm, 4x1, Gold, TH", Color=Black, Current_A=3A, Manufacturer="Sullins Connector Solutions", Supplier Part Number 1=S1011E-04-ND, Voltage_V=1.8kV
L1A L1B L1C L1D L1E L2A L2B L2C L2D L2E L3 L4: library part CMP-0064404-2, "Inductor, Shielded Drum Core, Ferrite, 100 uH, 0.3 A, 0.52 ohm, SMD", Manufacturer="Wurth Elektronik", Supplier Part Number 1=732-1111-1-ND, Value1="0.52 ohm", Value2=0.3A, ValueDisplayed=100uH
L5A L5B: library part CMP-0089502-2, "Power Inductor (SMD), 4.7 µH, 5.1 A, Shielded, 4.5 A, XAL40xx Series, 4mm x 4mm x 3.1mm", Manufacturer=Coilcraft, Mouser Part Number=994-XAL4030-472MEC, Operating Temperature Range="to +165°C", Self Resonant Frequency=36MHz, Test Frequency=1MHz, Tolerance_%=20%
LBL1: library part CMP-0003625-1, "Thermal Transfer Printable Labels, 0.650\" W x 0.200\" H - 10,000 per roll", Manufacturer=Brady, Supplier Part Number 1=97C5133
Logo2: library part CMP-0074844-1
Logo3: library part CMP-0074847-1, "FCC_disclaimer"
Logo4: library part CMP-0074769-3, Manufacturer="Texas Instruments"
NT1A NT1B NT4A NT4B NT6A NT6B: library part CMP-0078142-4, "Single point connection between nets.", Manufacturer=N/A
NT2A NT2B NT2C NT2D NT2E NT3A NT3B NT3C NT3D NT3E NT5A NT5B NT5C NT5D NT5E NT7 NT8A NT8B NT9A NT9B NT10 NT10A NT10B NT11 NT12 NT13: library part CMP-0078142-6, "Single point connection between nets.", Manufacturer=N/A
Q2A Q2B: library part CMP-0000026-3, "MOSFET, P-CH, -20 V, -60 A, DQG0008A (VSON-CLIP-8)", Alternate Manufacturer=None, Manufacturer="Texas Instruments", Value1=0.006, Value2="10.8 nC"
Q3A Q3B: library part CMP-0067551-1, "MOSFET, N-CH, 30 V, 5.9 A, YJK0003A (PICOSTAR-3)", Alternate Manufacturer=None, Manufacturer="Texas Instruments", Supplier Part Number 1=296-45068-1-ND, Value1="0.033 ohm", Value2="1.9 nC"
R1A R1B R2A R2B R3A R3B R4A R4B R5A R5B R6A R6B: library part CMP-0093037-1, "Thin Film Resistors RN 0603 49.9KΩ 0.1% 10ppm/°C", Manufacturer="TE Connectivity", Operating Temperature Range="-55°C to +155°C", Power_W=63mW, TempCo=10ppm/°C, Tolerance_%=0.1%
R7A R7B R143A R143B: library part CMP-0022650-2, "RES, 909, 1%, 0.1 W, 0603", Manufacturer=Vishay-Dale, Power_W=100mW, Supplier Part Number 1=541-909HCT-ND, TempCo="100 ppm/C", Tolerance_%=1%, Value2=0.1W, Value_Code=909R, ValueDisplayed=909
R8A R8B R8C R8D R8E R9A R9B R9C R9D R9E R10 R11 R12 R20A R20B R20C R20D R20E R29 R33 R39A R39B: library part CMP-0021999-4, "RES, 10.2 k, 1%, 0.1 W, AEC-Q200 Grade 0, 0603", Manufacturer=Vishay-Dale, Power_W=100mW, Supplier Part Number 1=541-10.2KHCT-ND, TempCo="100 ppm/C", Tolerance_%=1%, Value2=0.1W, Value_Code=10k2, ValueDisplayed=10.2k
R13A R13B: library part CMP-0022202-4, "RES, 205 k, 1%, 0.1 W, AEC-Q200 Grade 0, 0603", Manufacturer=Vishay-Dale, Power_W=100mW, Supplier Part Number 1=541-205KHCT-ND, TempCo="100 ppm/C", Tolerance_%=1%, Value2=0.1W, Value_Code=205k, ValueDisplayed=16.2k
R14 R17A R17B R17C R17D R17E R19 R32 R50 R53 R54 R55 R56 R57 R58 R59 R60 R61 R62 R63 R64 R65: library part CMP-0022341-4, "RES, 33.2, 1%, 0.1 W, AEC-Q200 Grade 0, 0603", Manufacturer=Vishay-Dale, Power_W=100mW, Supplier Part Number 1=541-33.2HCT-ND, TempCo="100 ppm/C", Tolerance_%=1%, Value2=0.1W, Value_Code=33R2, ValueDisplayed=33.2
R15 R16A R16B R16C R16D R16E R18A R18B R18C R18D R18E R30: library part CMP-0022170-4, "RES, 1.00, 1%, 0.1 W, AEC-Q200 Grade 0, 0603", Manufacturer=Vishay-Dale, Power_W=100mW, Supplier Part Number 1=52K8059, TempCo="100 ppm/C", Tolerance_%=1%, Value2=0.1W, Value_Code=1R00, ValueDisplayed=1.00
R21 R22A R22B R22C R22D R22E R23A R23B R23C R23D R23E R24A R24B R24C R24D R24E R25A R25B R25C R25D R25E R27 R34 R35: library part CMP-0022500-4, "RES, 56.2, 1%, 0.1 W, AEC-Q200 Grade 0, 0603", Manufacturer=Vishay-Dale, Power_W=100mW, Supplier Part Number 1=541-56.2HCT-ND, TempCo="100 ppm/C", Tolerance_%=1%, Value2=0.1W, Value_Code=56R2, ValueDisplayed=56.2
R26A R26B: library part CMP-0022079-4, "RES, 16.2 k, 1%, 0.1 W, AEC-Q200 Grade 0, 0603", Manufacturer=Vishay-Dale, Power_W=100mW, Supplier Part Number 1=541-16.2KHCT-ND, TempCo="100 ppm/C", Tolerance_%=1%, Value2=0.1W, Value_Code=16k2, ValueDisplayed=16.2k
R28A R28B: library part CMP-0022202-4, "RES, 205 k, 1%, 0.1 W, AEC-Q200 Grade 0, 0603", Manufacturer=Vishay-Dale, Power_W=100mW, Supplier Part Number 1=541-205KHCT-ND, TempCo="100 ppm/C", Tolerance_%=1%, Value2=0.1W, Value_Code=205k
R31A R31B: library part CMP-0016745-3, "RES, 1.00, 1%, 0.25 W, AEC-Q200 Grade 0, 1206", Manufacturer=Vishay-Dale, Power_W=250mW, Supplier Part Number 1=53K1855, TempCo="100 ppm/C", Tolerance_%=1%, Value2=0.25W, Value_Code=1R00, ValueDisplayed=1.00
R34A R34B: library part CMP-0022583-4, "RES, 732 k, 1%, 0.1 W, AEC-Q200 Grade 0, 0603", Manufacturer=Vishay-Dale, Power_W=100mW, Supplier Part Number 1=541-732KHCT-ND, TempCo="100 ppm/C", Tolerance_%=1%, Value2=0.1W, Value_Code=732k
R36A R36B: library part CMP-0021990-4, "RES, 100 k, 1%, 0.1 W, AEC-Q200 Grade 0, 0603", Manufacturer=Vishay-Dale, Power_W=100mW, Supplier Part Number 1=541-100KHCT-ND, TempCo="100 ppm/C", Tolerance_%=1%, Value2=0.1W, Value_Code=100k
R37A R37B: library part CMP-0022632-4, "RES, 88.7 k, 1%, 0.1 W, AEC-Q200 Grade 0, 0603", Manufacturer=Vishay-Dale, Power_W=100mW, Supplier Part Number 1=541-88.7KHCT-ND, TempCo="100 ppm/C", Tolerance_%=1%, Value2=0.1W, Value_Code=88k7, ValueDisplayed=88.7k
R38A R38B: library part CMP-0022268-4, "RES, 2.00 k, 1%, 0.1 W, AEC-Q200 Grade 0, 0603", Manufacturer=Vishay-Dale, Power_W=100mW, Supplier Part Number 1=541-2.00KHCT-ND, TempCo="100 ppm/C", Tolerance_%=1%, Value2=0.1W, Value_Code=2k00, ValueDisplayed=2.00k
R40A R40B R149A R149B: library part CMP-0120446-1, "100 kOhms ±0.1% 0.05W, 1/20W Chip Resistor 0201 (0603 Metric) Thick Film", Digikey Part Number=13-RE0201BRE07100KLCT-ND, Manufacturer=Yageo, Mouser Part Number=603-RE0201BRE07100KL, Operating Temperature Range="-55°C to +155°C", Power_W=50mW, TempCo=50ppm/°C, Tolerance_%=0.1%
R41A R41B: library part CMP-0023626-1, "RES, 10.0 k, 0.01%, 0.063 W, 0603", Manufacturer="Stackpole Electronics Inc", Power_W=63mW, Supplier Part Number 1=RNCF0603TKY10K0CT-ND, TempCo="5 ppm/C", Tolerance_%=0.01%, Value2=0.063W, Value_Code=10k0, ValueDisplayed=10.0k
R42A R42B R43A R43B: library part CMP-0022018-4, "RES, 11.5 k, 1%, 0.1 W, AEC-Q200 Grade 0, 0603", Manufacturer=Vishay-Dale, Power_W=100mW, Supplier Part Number 1=541-11.5KHCT-ND, TempCo="100 ppm/C", Tolerance_%=1%, Value2=0.1W, Value_Code=11k5, ValueDisplayed=11.5k
R44A R44B R46A R46B: library part CMP-0022634-4, "RES, 8.06 k, 1%, 0.1 W, AEC-Q200 Grade 0, 0603", Manufacturer=Vishay-Dale, Power_W=100mW, Supplier Part Number 1=541-8.06KHCT-ND, TempCo="100 ppm/C", Tolerance_%=1%, Value2=0.1W, Value_Code=8k06, ValueDisplayed=8.06k
R45A R45B: library part CMP-0022453-4, "RES, 4.42 k, 1%, 0.1 W, AEC-Q200 Grade 0, 0603", Manufacturer=Vishay-Dale, Power_W=100mW, Supplier Part Number 1=541-4.42KHCT-ND, TempCo="100 ppm/C", Tolerance_%=1%, Value2=0.1W, Value_Code=4k42, ValueDisplayed=4.42k
R47A R47B: library part CMP-0022426-4, "RES, 44.2 k, 1%, 0.1 W, AEC-Q200 Grade 0, 0603", Manufacturer=Vishay-Dale, Power_W=100mW, Supplier Part Number 1=541-44.2KHCT-ND, TempCo="100 ppm/C", Tolerance_%=1%, Value2=0.1W, Value_Code=44k2, ValueDisplayed=44.2k
R48A R48B: library part CMP-0022558-4, "RES, 6.04 k, 1%, 0.1 W, AEC-Q200 Grade 0, 0603", Manufacturer=Vishay-Dale, Power_W=100mW, Supplier Part Number 1=541-6.04KHCT-ND, TempCo="100 ppm/C", Tolerance_%=1%, Value2=0.1W, Value_Code=6k04, ValueDisplayed=6.04k
R49A R49B: library part CMP-0022454-4, "RES, 4.53 k, 1%, 0.1 W, AEC-Q200 Grade 0, 0603", Manufacturer=Vishay-Dale, Power_W=100mW, Supplier Part Number 1=541-4.53KHCT-ND, TempCo="100 ppm/C", Tolerance_%=1%, Value2=0.1W, Value_Code=4k53, ValueDisplayed=4.53k
R51A R51B R52A R52B: library part CMP-0025697-3, "RES, 0, 5%, 0.1 W, 0603", Manufacturer=Vishay-Dale, PartNumber=CRCW06030000Z0EA, Power_W=100mW, Supplier Part Number 1=541-0.0GCT-ND, TempCo="200 ppm/C", Tolerance_%=5%, Value2=0.1W, Value_Code=0000, ValueDisplayed=0
R145A R145B: library part CMP-0065353-2, "RES, 100 k, .5%, .0625 W, 0603", Manufacturer="Susumu Co Ltd", Power_W=62.5mW, Supplier Part Number 1=RR08P100KDCT-ND, TempCo="25 ppm/C", Tolerance_%=0.5%, Value1=.5%, Value2=.0625W, Value_Code=100k
T1A T1B T1C T1D T1E T2A T2B T2C T2D T2E T3 T4: library part CMP-0030422-2, "Transformers, Gate Drive , 785uH, SMT", Manufacturer="Pulse Engineering", Supplier Part Number 1=553-1776-1-ND, ValueDisplayed=785uH
TP1 TP2 TP3 TP4 TP5 TP7 TP8 TP9 TP10 TP11 TP16A TP16B TP16C TP16D TP16E TP17A TP17B TP17C TP17D TP17E TP18A TP18B TP18C TP18D TP18E TP19A TP19B TP19C TP19D TP19E TP21A TP21B TP21C TP21D TP21E TP22A TP22B TP22C TP22D TP22E TP23A TP23B TP23C TP23D TP23E TP24A TP24B TP24C TP24D TP24E TP25A TP25B TP25C TP25D TP25E TP26A TP26B TP26C TP26D TP26E: library part CMP-0055141-2, "Test Point, Miniature, Yellow, TH", Color=Yellow, Manufacturer="Keystone Electronics", Supplier Part Number 1=36-5004-ND
TP6 TP20A TP20B TP20C TP20D TP20E TP38A TP38B TP39A TP39B: library part CMP-0055138-2, "Test Point, Miniature, Black, TH", Color=Black, Manufacturer="Keystone Electronics", Supplier Part Number 1=36-5001-ND
TP27A TP27B TP30A TP30B: library part CMP-0055137-1, "Test Point, Miniature, Red, TH", Color=Red, Manufacturer=Keystone, Supplier Part Number 1=36-5000-ND
TP29A TP29B: library part CMP-0055138-1, "Test Point, Miniature, Black, TH", Color=Black, Manufacturer=Keystone, Supplier Part Number 1=36-5001-ND
TP33A TP33B TP36A TP36B TP37A TP37B: library part CMP-0055137-2, "Test Point, Miniature, Red, TH", Color=Red, Manufacturer="Keystone Electronics", Supplier Part Number 1=36-5000-ND
TP34A TP34B TP35AA TP35AB: library part CMP-0055139-2, "Test Point, Miniature, White, TH", Color=White, Manufacturer="Keystone Electronics", Supplier Part Number 1=36-5002-ND
U2 U10A U10B U10C U10D U10E: library part CMP-0051824-2, "Dual Bus Buffer Gate With 3-State Outputs, DCU0008A (VSSOP-8)", F @ Nom Voltage(Max)(Mhz)=150, Generic Part Number=SN74LVC2G126, ICC @ Nom Voltage(Max)(mA)=0.01, Manufacturer="Texas Instruments", Operating Temperature Range="-40 to 125 C", Rating=Catalog, tpd @ Nom Voltage(Max)(ns)=9.8,4.9,4,3.2, Voltage(Nom)(V)=1.8,2.5,3.3,5
U3 U9: library part CMP-0074780-3, "5-V RS-485 Transceivers With +/-18-kV IEC ESD Protection, DGK0008A (VSSOP-8)", Alternate Manufacturer="Texas Instruments", Alternate PartNumber=THVD1550DGK
U4A U4B U4C U4D U4E U5A U5B U5C U5D U5E: library part CMP-0065059-3, "3.3-V to 5-V RS-485 Transceivers With +/-18-kV IEC ESD Protection, D0008A (SOIC-8)", Alternate Manufacturer="Texas Instruments", Alternate PartNumber=THVD1450DR, Operating Temperature Range="-40 to 125 C"
U6A U6B: library part CMP-0085596-1, "15-V Output Voltage Non-Sync Boost Converter, DBV0006A (SOT-23-6)", Alternate Manufacturer="Texas Instruments", Alternate PartNumber=TLV61048DBVT
U8A U8B: library part CMP-0088329-1, "2.7- 23V, 5.5 A, 28 mΩ Reverse Current Blocking eFuse with Input Reverse Polarity Protection", Manufacturer="Texas Instruments", Max Supply Voltage=23V, Min Supply Voltage=2.7V, Nominal Supply Current=0.5-6A, Operating Temperature Range="-40°C to +125°C", Output Voltage=42V, Threshold Voltage=1.2/1.1V
U11A U11B: library part CMP-0092464-2, "3-V to 17-V, High Efficiency and Low IQ Buck Converter Module in MicroSiP Package with Integrated Inductor", Manufacturer="Texas Instruments", Max Supply Voltage=17V, Min Supply Voltage=3V, Nominal Supply Current=8mA, Operating Temperature Range="-55°C to +125°C", Output Voltage=0.4-5.5V, Switching Frequency=1/2.5MHz
U14A U14B: library part CMP-0092323-1, "60-V Input, 1-V to 16-V Output, 600-mA Power Module in Enhanced HotRod QFN Package", Manufacturer="Texas Instruments", Max Supply Voltage=60V, Min Supply Voltage=4.2V, Operating Temperature Range="-55°C to +125°C", Output Voltage=1-16V, Switching Frequency=1MHz
U46A U46B: "IC 6-BIT BIDIRECTIONAL VOLTAGE-LEVEL TRANSLATOR VQFN16", Mfr_name="TEXAS INSTRUMENTS", Mfr_part_number=TXB0106RGYR, Mistral Part No=141018020001-R, Package=VQFN16, Temperature=-40°C+85°C, Tolerance=NA
ZZ1: library part CMP-0003616-3
ZZ2: library part CMP-0077236-1
ZZ3: library part CMP-0077237-1
ZZ4: library part CMP-0077238-1

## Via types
v1: diameter 0.457/0.457/0.457/0.457 (per signal layer), hole 0.203, Top Layer to Bottom Layer, tented both sides, 68 vias
v2: diameter 0.864, hole 0.406, Top Layer to Mid-Layer 1, 51 vias
v3: diameter 0.5, hole 0.2, Top Layer to Bottom Layer, 40 vias
v4: diameter 0.864, hole 0.406, Top Layer to Bottom Layer, 40 vias
v5: diameter 0.7, hole 0.3, Top Layer to Bottom Layer, 36 vias
v6: diameter 0.61, hole 0.3, Top Layer to Bottom Layer, 29 vias
v7: diameter 1.524, hole 0.762, Top Layer to Bottom Layer, tented both sides, 12 vias
v8: diameter 0.203, hole 0.203, Top Layer to Bottom Layer, tented both sides, 8 vias
v9: diameter 1.016, hole 0.508, Top Layer to Bottom Layer, tented both sides, 6 vias
v10: diameter 0.61, hole 0.3, Top Layer to Mid-Layer 1, 3 vias
v11: diameter 0.457, hole 0.203, Top Layer to Mid-Layer 1, tented both sides, 2 vias
v12: diameter 0.5, hole 0.2, Top Layer to Bottom Layer, tented both sides, 2 vias
v13: diameter 0.7, hole 0.203, Top Layer to Mid-Layer 1, tented both sides, 1 vias
v14: diameter 0.7, hole 0.254, Top Layer to Bottom Layer, 1 vias
v15: diameter 0.7, hole 0.254, Top Layer to Mid-Layer 1, 1 vias
v16: diameter 0.457/0.457 (per signal layer), hole 0.203, Top Layer to Mid-Layer 1, tented both sides, 1 vias

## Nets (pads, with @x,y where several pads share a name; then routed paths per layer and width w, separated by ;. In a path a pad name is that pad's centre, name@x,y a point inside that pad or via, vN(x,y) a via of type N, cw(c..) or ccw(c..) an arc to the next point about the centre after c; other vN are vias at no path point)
5V0_EXTERNAL_1: J4.1 J13.1 NT4A.1 | length 172.4
  Top Layer w0.6: NT4A.1@67.19,92.387 69.124,92.387 69.243,92.267 v6(69.246,92.267)
  Bottom Layer w1: v6(69.246,92.267) 69.583,91.93 123.499,91.93 129.216,97.647 129.216,101.896 J4.1@132.988,105.667 135.351,103.304 135.351,62.121 129.804,56.574 129.804,37.247 132.018,35.033 132.018,20.474 129.804,18.259 129.804,15.43 J13.1@131.868,13.365
5V0_EXTERNAL_2: J4.2 J4.3 J14.1 NT4B.1 | length 73.6
  Top Layer w1: NT4B.1@131.684,93.215 131.684,97.688 134.968,100.973 134.968,107.357 134.223,108.102 133.093,108.102 J4.2@132.988,108.207
  Bottom Layer w1: J14.1@128.733,159.25 131.392,159.25 134.642,156 134.642,112.401 J4.3@132.988,110.747 J4.2@132.988,108.207
11V0_12V0A: C113A.1 D2A.1 NT1A.1 U11A.1 U11A.2 U11A.3 | length 15
  Top Layer w0.254: U11A.2@54.874,107.105 U11A.3@55.374,107.105
  Top Layer w0.508: C113A.1@53.841,104.796 53.841,105.046 54.211,105.416 U11A.1@54.211,107.105 U11A.2@54.874,107.105
  Top Layer w0.762: NT1A.1@50.953,99.955 55.7,99.955 56.147,100.401 D2A.1@56.147,101.861 56.186,101.9 56.186,103.184 55.74,103.631 54.756,103.631 53.841,104.546 C113A.1@53.841,104.796
11V0_12V0B: C113B.1 D2B.1 NT1B.1 U11B.1 U11B.2 U11B.3 | length 15.1
  Top Layer w0.254: U11B.2@109.92,111.432 U11B.3@110.42,111.432
  Top Layer w0.508: U11B.2@109.92,111.432 U11B.1@109.258,111.432 109.258,109.743 108.888,109.373 C113B.1@108.888,109.123 108.888,108.873 109.902,107.859 110.685,107.859 111.193,107.351 D2B.1@111.193,106.189 111.193,106.036 115.447,101.783 NT1B.1@115.447,100.783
